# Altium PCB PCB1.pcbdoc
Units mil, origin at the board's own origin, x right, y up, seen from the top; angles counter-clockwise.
Board outline 2165 x 2756 mil, 2 copper layers (Top Layer, Bottom Layer), stack 62.206 mil thick; 92 components, 43 nets, 262 pads, 79 vias.
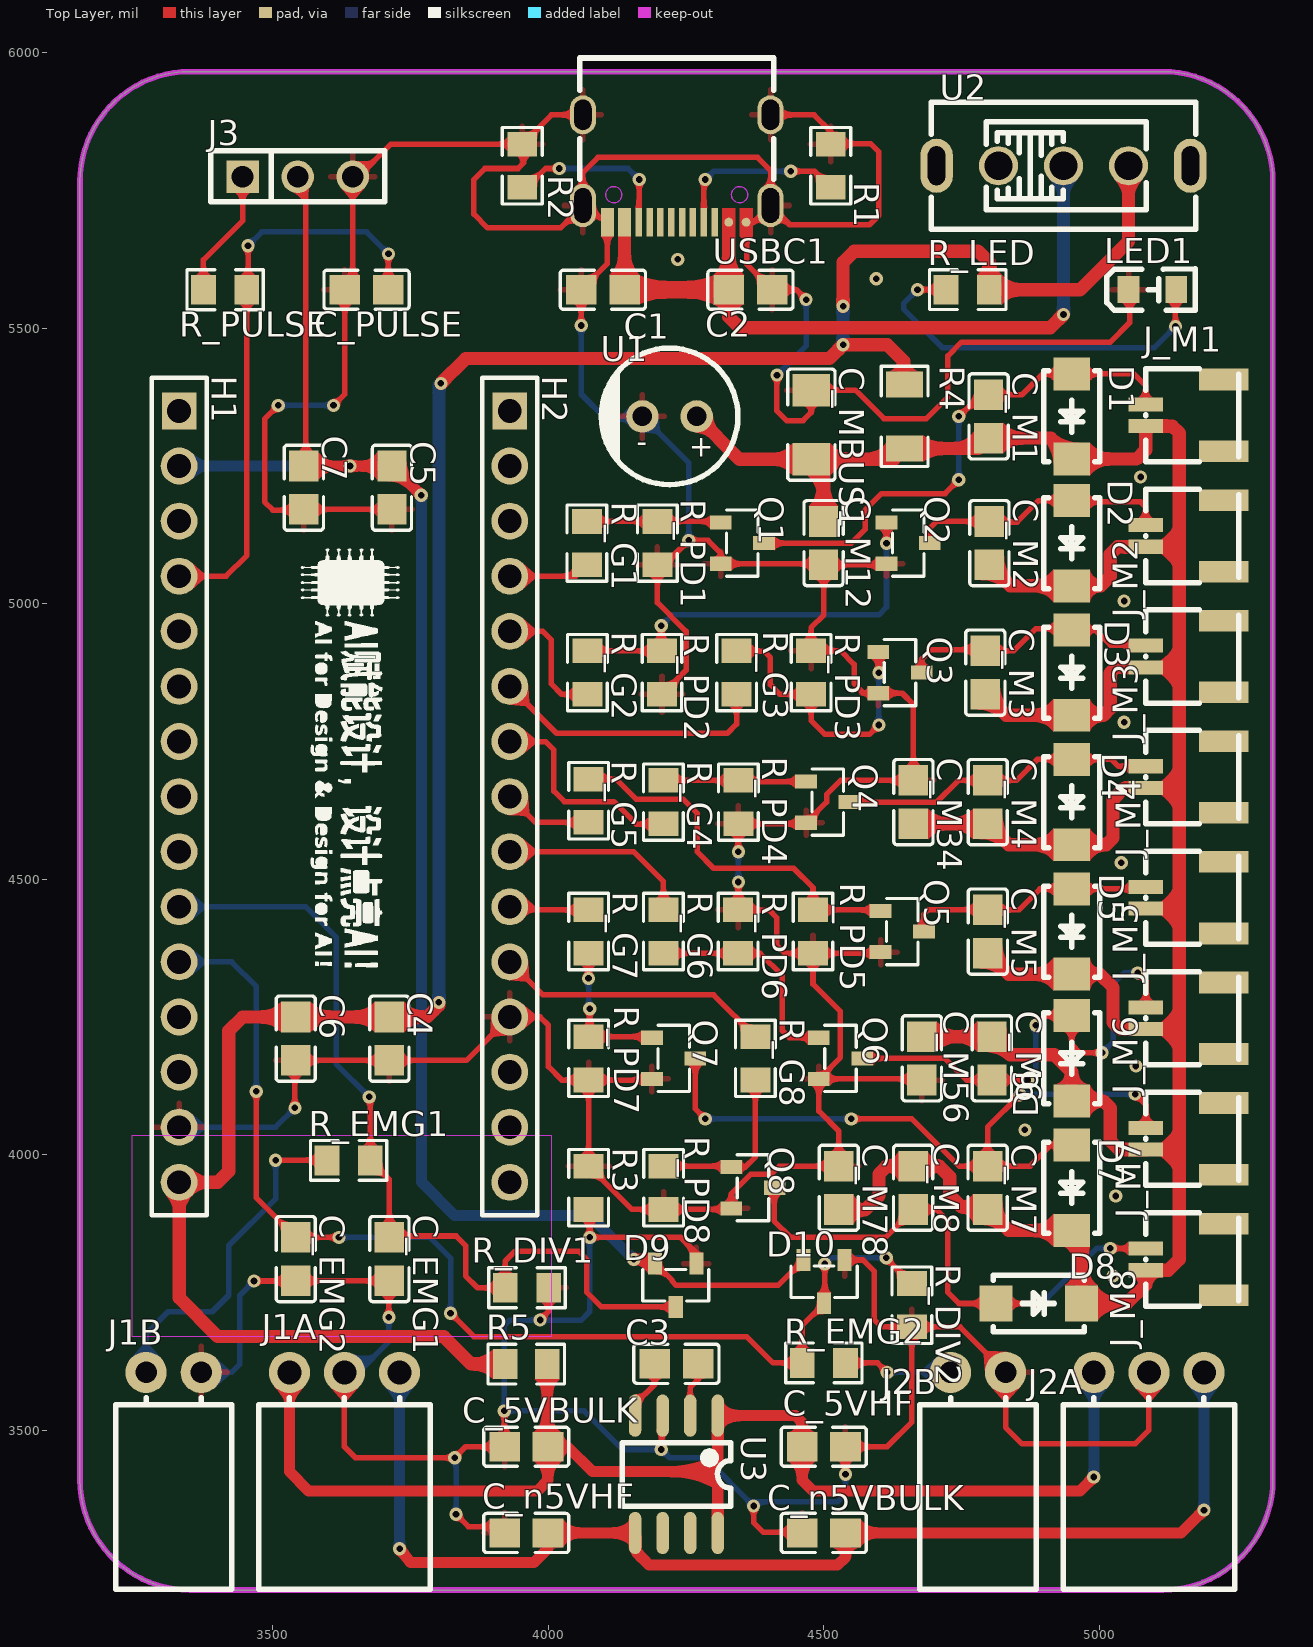
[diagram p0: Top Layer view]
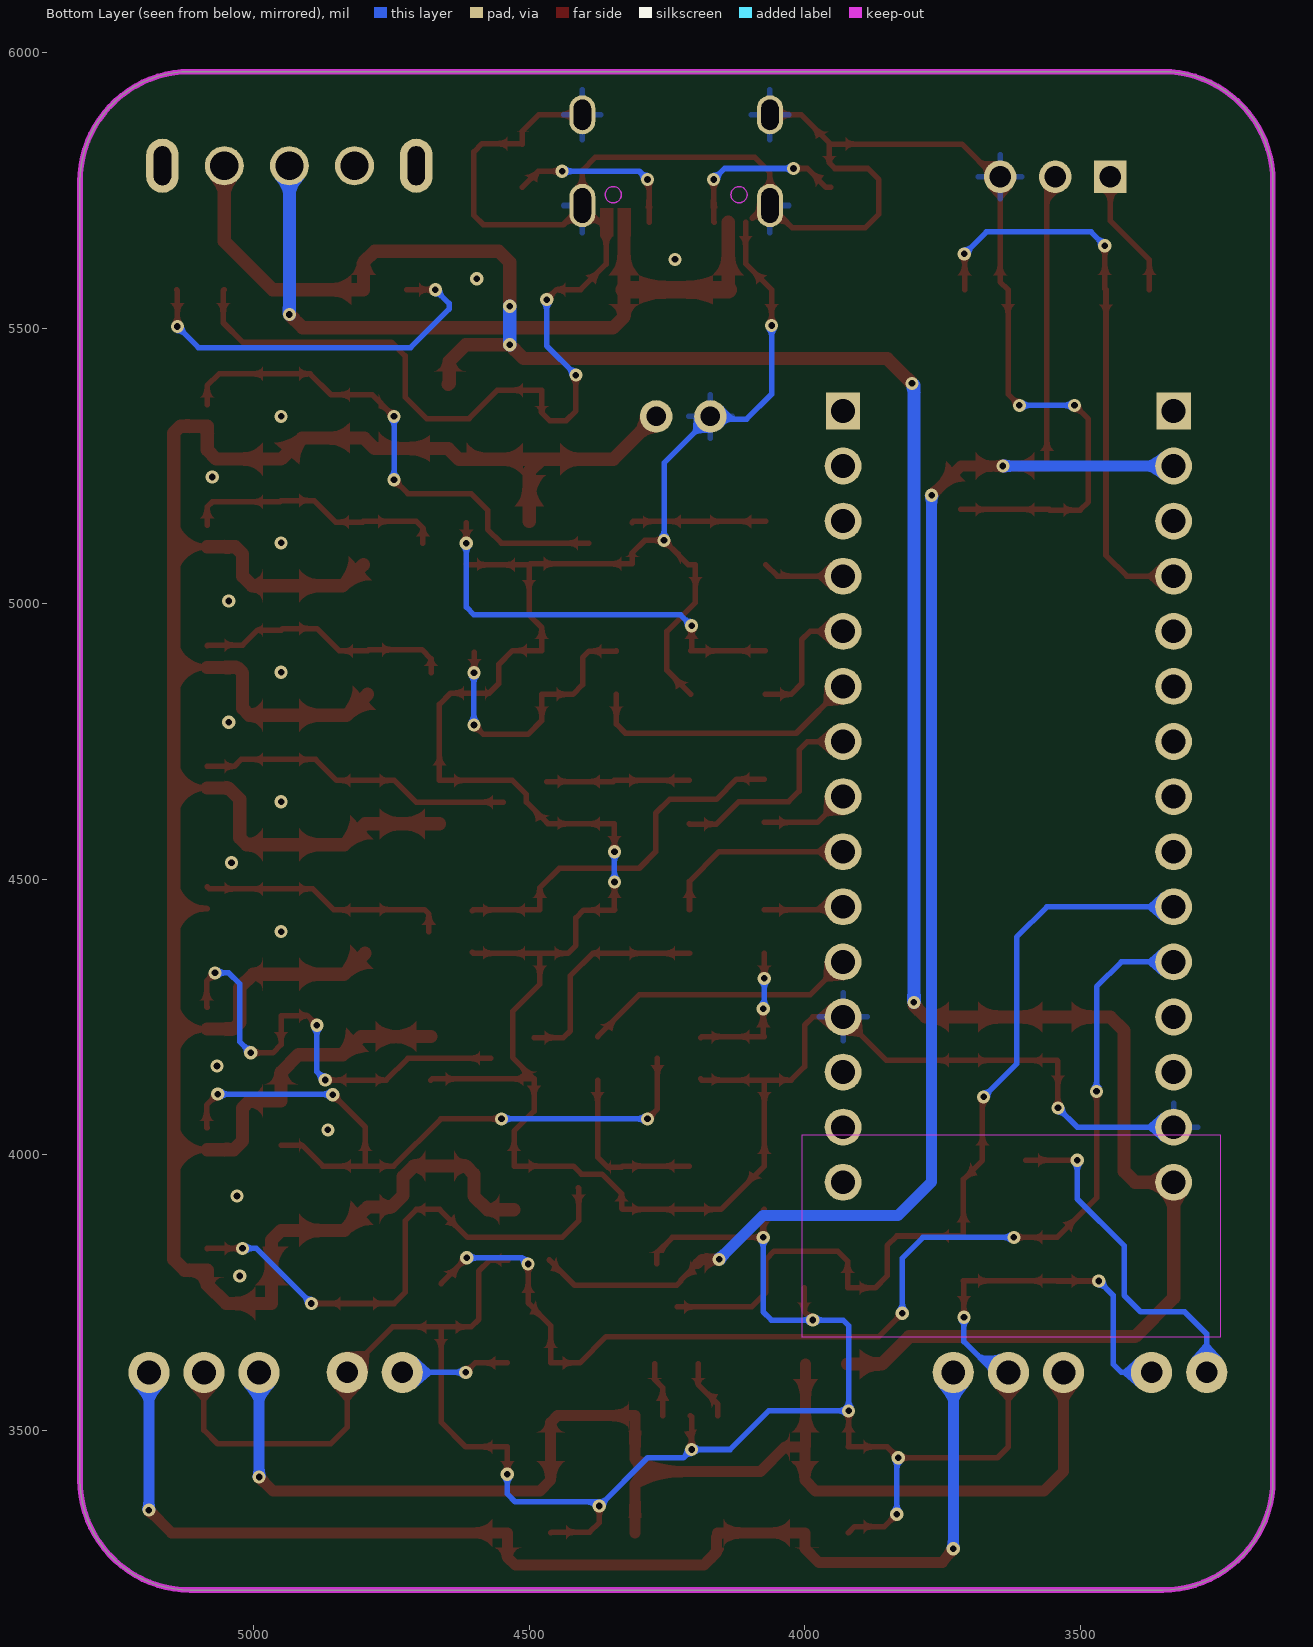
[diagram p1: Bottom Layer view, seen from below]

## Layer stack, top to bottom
Top Solder Mask Layer: solder mask 0.394, Dk 3.3
Top Layer: signal copper 1.379
Dielectric1: surface 59.449, FR4, Dk 4.5
Bottom Layer: signal copper 1.378
Bottom Solder Mask Layer: solder mask 0.394, Dk 3.3

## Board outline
3350.02,5966 5115.02,5966 cw(c5115.02,5766) 5315.02,5766 5315.02,3410 cw(c5115.02,3410) 5115.02,3210 3350.02,3210 cw(c3350.02,3410) 3150.02,3410 3150.02,5766 cw(c3350.02,5766)

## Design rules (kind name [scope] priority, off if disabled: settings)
BoardOutlineClearance copperThickness1oz [All] p0: genericclearance=10 ignorepadtopadclearanceinfootprint=FALSE except(0: Arc-SplitContinuation Track-SplitContinuation SMDPad-SplitContinuation THPad-SplitContinuation Via-SplitContinuation Fill-SplitContinuation Poly-SplitContinuation Region-SplitContinuation Text-SplitContinuation)
BoardOutlineClearance copperThickness2oz [All] p0: genericclearance=10 ignorepadtopadclearanceinfootprint=FALSE except(0: Arc-SplitContinuation Track-SplitContinuation SMDPad-SplitContinuation THPad-SplitContinuation Via-SplitContinuation Fill-SplitContinuation Poly-SplitContinuation Region-SplitContinuation Text-SplitContinuation)
BoardOutlineClearance otherClearance [All] p0: genericclearance=10 ignorepadtopadclearanceinfootprint=FALSE except(0: Arc-SplitContinuation Track-SplitContinuation SMDPad-SplitContinuation THPad-SplitContinuation Via-SplitContinuation Fill-SplitContinuation Poly-SplitContinuation Region-SplitContinuation Text-SplitContinuation)
Clearance copperThickness1oz [All] p1: gap=7 ignorepadtopadclearanceinfootprint=FALSE
Clearance copperThickness2oz [All] p1: gap=7 ignorepadtopadclearanceinfootprint=FALSE
Clearance otherClearance [All] p1: gap=7 ignorepadtopadclearanceinfootprint=FALSE
DiffPairsRouting differentialPair [All] p1: maxuncoupledlength=10 minlimit=6 maxlimit=Infinity mostfreqgap=6 toplayer_minwidth=5 toplayer_prefwidth=10 toplayer_maxwidth=100 bottomlayer_minwidth=5 bottomlayer_prefwidth=10 bottomlayer_maxwidth=100
PasteMaskExpansion pasteMaskExpansion [All] p1: expansion=0
PlaneConnect innerPlane [All] p1: planeconnectstyle=Relief reliefexpansion=20 reliefentries=4 reliefconductorwidth=10 reliefairgap=10
PolygonConnect copperRegion [All] p1: connectstyle=Relief reliefentries=4 reliefconductorwidth=10 polygonreliefangle="90 Angle" airgapwidth=10
RoutingVias viaSize [All] p1: viastyle="Through Hole" holewidth=12.0078 minholewidth=11.811 maxholewidth=248.0314 width=12.0078 minwidth=11.811 maxwidth=248.0314
SolderMaskExpansion solderMaskExpansion [IsVia] p1: useseparateexpansions=TRUE expansion=-1000 expansionbottom=-1000
SolderMaskExpansion solderMaskExpansion [All] p2: useseparateexpansions=TRUE expansion=2 expansionbottom=2
Width copperThickness1oz [All] p1: maxlimit=100 minlimit=5 preferedwidth=10
Width copperThickness2oz [All] p1: maxlimit=100 minlimit=8 preferedwidth=10

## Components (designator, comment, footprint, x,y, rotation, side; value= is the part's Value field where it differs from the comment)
C1 "100nF" C0805 4099.12,5570 r180 top locked
C2 "10uF" C0805 4366.92,5569.99 r0 top locked
C3 "10uF" C0805 4232.52,3620.53 r180 top locked
C4 "10uF" C0805 3711.55,4210.62 r270 top locked
C5 "10uF" C0805 3716.25,5210.65 r270 top locked
C6 "100nF" C0805 3541.55,4210.62 r270 top locked
C7 "100nF" C0805 3556.25,5210.65 r270 top locked
C_5VBULK "10uF" C0805 3960.02,3469.96 r0 top locked
C_5VHF "100nF" C0805 4500,3470 r180 top locked
C_EMG1 "47nF" C0805 3711.55,3810.63 r270 top locked
C_EMG2 "47nF" C0805 3541.55,3810.63 r270 top locked
C_M1 "100nF" C0805 4799.05,5340 r270 top locked
C_M2 "100nF" C0805 4800.53,5110 r270 top locked
C_M3 "100nF" C0805 4793.18,4875 r270 top locked
C_M4 "100nF" C0805 4797.49,4640 r270 top locked
C_M5 "100nF" C0805 4797.67,4405 r270 top locked
C_M6 "100nF" C0805 4805.19,4175 r90 top locked
C_M7 "100nF" C0805 4797.32,3940 r270 top locked
C_M8 "100nF" C0805 4662.22,3940 r90 top locked
C_M12 "10uF" C0805 4499.51,5110 r90 top locked
C_M34 "10uF" C0805 4662.57,4640 r270 top locked
C_M56 "10uF" C0805 4677.97,4175 r90 top locked
C_M78 "10uF" C0805 4527.12,3940 r270 top locked
C_MBUS1 "CC1206X5R10V107MN" C1206 4477.32,5325 r270 top locked
C_n5VBULK "10uF" C0805 4500,3313.49 r0 top locked
C_n5VHF "100nF" C0805 3960.02,3313.5 r0 top locked
C_PULSE "100nF" C0805 3670.02,5570 r0 top locked
D1 "SS14" SMA_L4.2-W2.6-LS5.0-RD_1 4950.02,5340 r90 top locked
D2 "SS14" SMA_L4.2-W2.6-LS5.0-RD_1 4950.02,5110 r90 top locked
D3 "SS14" SMA_L4.2-W2.6-LS5.0-RD_1 4950.02,4875 r90 top locked
D4 "SS14" SMA_L4.2-W2.6-LS5.0-RD_1 4950.02,4640 r90 top locked
D5 "SS14" SMA_L4.2-W2.6-LS5.0-RD_1 4950.02,4405 r90 top locked
D6 "SS14" SMA_L4.2-W2.6-LS5.0-RD_1 4950.02,4175 r90 top locked
D7 "SS14" SMA_L4.2-W2.6-LS5.0-RD_1 4950.02,3940 r90 top locked
D8 "SS14" SMA_L4.2-W2.6-LS5.0-RD_1 4890.02,3730 r180 top locked
D9 "BAT54SLT1" SOT-23-3_L2.9-W1.3-P1.90-LS2.4-BR 4231.25,3763.14 r90 top locked
D10 "BAT54SLT1" SOT-23-3_L2.9-W1.3-P1.90-LS2.4-BR 4500.44,3769.57 r90 top locked
H1 "排母1X15P 2.54mm" HDR-TH_15P-P2.54-V-F 3330.02,4650 r270 top locked
H2 "排母1X15P 2.54mm" HDR-TH_15P-P2.54-V-F 3930.02,4650 r270 top locked
J1A "PM254-1-03-W-8.5" HDR-TH_3P-P2.54-H-F-W10.0-N 3630.02,3605 r0 top locked
J1B "PM254-1-02-W-8.5" HDR-TH_2P-P2.54-H-F-W10.0-N 3320.02,3605 r0 top locked
J2A "PM254-1-03-W-8.5" HDR-TH_3P-P2.54-H-F-W10.0-N 5090.02,3605 r0 top locked
J2B "PM254-1-02-W-8.5" HDR-TH_2P-P2.54-H-F-W10.0-N 4780.02,3605 r0 top locked
J3 "排母2.54mm 1X3pin" HDR-TH_3P-P2.54_CS-1165SDIG 3545.02,5775 r0 top locked
J_M1 "1.0WT-2P" CONN-SMD_2P-P1.00-WT 5155.02,5341.97 r90 top locked
J_M2 "1.0WT-2P" CONN-SMD_2P-P1.00-WT 5155.02,5123.12 r90 top locked
J_M3 "1.0WT-2P" CONN-SMD_2P-P1.00-WT 5155.02,4904.26 r90 top locked
J_M4 "1.0WT-2P" CONN-SMD_2P-P1.00-WT 5155.02,4685.41 r90 top locked
J_M5 "1.0WT-2P" CONN-SMD_2P-P1.00-WT 5155.02,4466.56 r90 top locked
J_M6 "1.0WT-2P" CONN-SMD_2P-P1.00-WT 5155.02,4247.71 r90 top locked
J_M7 "1.0WT-2P" CONN-SMD_2P-P1.00-WT 5155.02,4028.85 r90 top locked
J_M8 "1.0WT-2P" CONN-SMD_2P-P1.00-WT 5155.02,3810 r90 top locked
LED1 "NCD0805R1" LED0805-RD 5096.5,5570.04 r0 top locked
Q1 "AO3400A" SOT-23-3_L2.9-W1.3-P1.90-LS2.4-BR 4352.15,5110 r180 top locked
Q2 "AO3400A" SOT-23-3_L2.9-W1.3-P1.90-LS2.4-BR 4653.17,5110 r180 top locked
Q3 "AO3400A" SOT-23-3_L2.9-W1.3-P1.90-LS2.4-BR 4638.47,4875 r180 top locked
Q4 "AO3400A" SOT-23-3_L2.9-W1.3-P1.90-LS2.4-BR 4507.18,4640 r180 top locked
Q5 "AO3400A" SOT-23-3_L2.9-W1.3-P1.90-LS2.4-BR 4642.45,4405 r180 top locked
Q6 "AO3400A" SOT-23-3_L2.9-W1.3-P1.90-LS2.4-BR 4530.28,4175 r180 top locked
Q7 "AO3400A" SOT-23-3_L2.9-W1.3-P1.90-LS2.4-BR 4227.51,4175 r180 top locked
Q8 "AO3400A" SOT-23-3_L2.9-W1.3-P1.90-LS2.4-BR 4371.55,3940 r180 top locked
R1 "5.1kΩ" R0805 4512.64,5794.98 r90 top locked
R2 "5.1kΩ" R0805 3952.64,5794.98 r270 top locked
R3 "0Ω" R0805 4072.98,3940 r270 top locked
R4 "0Ω" R1206 4646.8,5340 r90 top locked
R5 "10Ω" R0805_NEW 3960.02,3620 r0 top locked
R_DIV1 "10kΩ" R0805 3961.18,3758.55 r180 top locked
R_DIV2 "10kΩ" R0805 4659.78,3726.89 r90 top locked
R_EMG1 "5.6kΩ" R0805 3637.64,3989.76 r0 top locked
R_EMG2 "5.6kΩ" R0805 4500.05,3622.17 r180 top locked
R_G1 "100Ω" R0805 4070.02,5110 r90 top locked
R_G2 "100Ω" R0805 4071.04,4875 r90 top locked
R_G3 "100Ω" R0805 4341.63,4875 r90 top locked
R_G4 "100Ω" R0805 4208.96,4640 r90 top locked
R_G5 "100Ω" R0805 4072.98,4642.52 r90 top locked
R_G6 "100Ω" R0805 4208.79,4405 r270 top locked
R_G7 "100Ω" R0805 4072.98,4405 r270 top locked
R_G8 "100Ω" R0805 4375.74,4175 r270 top locked
R_LED "1kΩ" R0805 4761.2,5570.05 r0 top locked
R_PD1 "10kΩ" R0805 4197.96,5110 r90 top locked
R_PD2 "10kΩ" R0805 4206.34,4875 r90 top locked
R_PD3 "10kΩ" R0805 4476.92,4875 r270 top locked
R_PD4 "10kΩ" R0805 4344.94,4640 r90 top locked
R_PD5 "10kΩ" R0805 4480.39,4405 r90 top locked
R_PD6 "10kΩ" R0805 4344.59,4405 r270 top locked
R_PD7 "10kΩ" R0805 4072.98,4175 r90 top locked
R_PD8 "10kΩ" R0805 4209.14,3940 r90 top locked
R_PULSE "1kΩ" R0805 3413.48,5569.96 r0 top locked
U1 "220uF±20%25V 6.3*11 2.5mm" CAP-TH_BD6.3-P2.50-D0.5-FD 4220.02,5340 r180 top locked
U2 "SS-12F44-G3" SW-TH_SS-12F44-G5_C2998807 4935.02,5795 r0 top locked
U3 "MAX660M/NOPB" SOIC-8_L5.0-W4.0-P1.27-LS6.1-BL 4232.52,3420 r180 top locked
USBC1 "TYPE-C-31-M-12" USB-C_SMD-TYPE-C-31-M-12_1 4233.02,5790 r180 top locked

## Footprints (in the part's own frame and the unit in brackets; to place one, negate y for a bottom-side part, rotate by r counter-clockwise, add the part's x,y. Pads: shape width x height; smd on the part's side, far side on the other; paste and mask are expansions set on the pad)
C0805 [mm]
  rect 1.41x1.35 smd paste-100 mask+0.051: 1(-1,0) 2(1,0)
  silkscreen extent -1.96,-0.9 1.96,0.9
C1206 [mm]
  rect 1.485x1.728 smd paste-100 mask+0.051: 1(-1.593,0) 2(1.593,0)
  silkscreen extent -2.56,-1.09 2.56,1.09
CAP-TH_BD6.3-P2.50-D0.5-FD [mm]
  round 1.5 hole 0.9 paste+0 mask+0.05: 1(-1.25,0) 2(1.25,0)
  silkscreen extent -3.15,-3.15 3.21,3.15
CONN-SMD_2P-P1.00-WT [mm]
  rect 0.65x1.6 smd paste+0 mask+0.05: 1(-0.5,1.8) 2(0.5,1.8)
  rect 1x2.3 smd paste+0 mask+0.05: 5(1.65,-1.8) 6(-1.65,-1.8)
  silkscreen extent -2.15,-2.5 2.15,1.8
HDR-TH_2P-P2.54-H-F-W10.0-N [mm]
  round 1.9 hole 1 paste+0 mask+0.05: 1(-1.27,0) 2(1.27,0)
  silkscreen extent -2.68,-10 2.68,-1.18
HDR-TH_3P-P2.54-H-F-W10.0-N [mm]
  round 1.9 hole 1.1 paste+0 mask+0.05: 1(-2.54,0) 2(0,0) 3(2.54,0)
  silkscreen extent -3.95,-10 3.95,-1.18
HDR-TH_3P-P2.54_CS-1165SDIG [mm]
  rect 1.5x1.5 hole 1: 1(-2.54,0)
  round 1.5 hole 1: 2(0,0) 3(2.54,0)
  silkscreen extent -4.02,-1.15 4.02,1.2
HDR-TH_15P-P2.54-V-F [mm]
  rect 1.7x1.575 hole 1.1: 1(-17.78,0)
  round 1.7 hole 1.1: 2(-15.24,0) 3(-12.7,0) 4(-10.16,0) 5(-7.62,0) 6(-5.08,0) 7(-2.54,0) 8(0,0) 9(2.54,0) 10(5.08,0) 11(7.62,0) 12(10.16,0) 13(12.7,0) 14(15.24,0) 15(17.78,0)
  silkscreen extent -19.3,-1.27 19.3,1.27
LED0805-RD [mm]
  rect 1x1.25 smd: 1(-1.1,0) 2(1.1,0)
  silkscreen extent -2.1,-0.95 1.98,0.96
R0805 [mm]
  rect 1.133x1.377 smd paste-100 mask+0.051: 1(-1,0) 2(1,0)
  silkscreen extent -1.76,-0.92 1.76,0.92
R0805_NEW [mil]
  rect 44.59x54.21 smd paste-3937.01 mask+2: 1(-38.04,0) 2(38.04,0)
  silkscreen extent -69,-36 69,36
R1206 [mil]
  rect 47.54x66.97 smd paste-3937.01 mask+2: 1(-58.22,0) 2(58.22,0)
  silkscreen extent -91,-42 91,42
SMA_L4.2-W2.6-LS5.0-RD_1 [mm]
  rect 1.52x1.68 smd: 1(-1.965,0) 2(1.965,0)
  silkscreen extent -2.1,-1.3 2.1,1.3
SOIC-8_L5.0-W4.0-P1.27-LS6.1-BL [mil]
  oval 22.38x76.78 smd: 1(-75,-106.5) 2(-25,-106.5) 3(25,-106.5) 4(75,-106.5) 5(75,106.5) 6(25,106.5) 7(-25,106.5) 8(-75,106.5)
  silkscreen extent -98,-58 98,58
SOT-23-3_L2.9-W1.3-P1.90-LS2.4-BR [mm]
  rect 1x0.65 smd: 1(1,-0.95) 2(1,0.95) 3(-1,0)
  silkscreen extent -0.73,-1.53 0.73,1.53
SW-TH_SS-12F44-G5_C2998807 [mm]
  round 1.8 hole 1.3: 1(-3,0) 2(0,0) 3(3,0)
  oval 1.5x2.5 hole 0.8 slot 1.8 at 90 deg: 4(5.85,0) 5(-5.85,0)
  silkscreen extent -6.1,-2.92 6.1,2.92
USB-C_SMD-TYPE-C-31-M-12_1 [mm]
  oval 1.2x2 hole 0.8 slot 1.6 at 90 deg: 1(4.325,1.706) 4(-4.325,1.706)
  oval 1.2x1.8 hole 0.8 slot 1.4 at 90 deg copper offset 0,0: 2(4.325,-2.474) 3(-4.325,-2.474)
  round 0.41 smd: A1B12(-3.2,2.474)
  round 0.411 smd: A4B9(-2.4,2.474)
  rect 0.3x1.3 smd paste-100 mask+0.051: A5(-1.25,2.474) A6(-0.25,2.474) A7(0.25,2.474) A8(1.25,2.474) B5(1.75,2.474) B6(0.75,2.474) B7(-0.75,2.474) B8(-1.75,2.474)
  rect 0.6x1.3 smd paste-100 mask+0.051: B1A12(3.2,2.474) B4A9(2.4,2.474)
  Top Layer region: -2.9,1.824 -2.9,3.124 -3.2,3.124 -3.2,3.124 -3.5,3.124 -3.5,1.824 -3.2,1.824 -3.2,1.824
  Top Layer region: -2.1,1.824 -2.1,3.124 -2.4,3.124 -2.4,3.124 -2.7,3.124 -2.7,1.824 -2.4,1.824 -2.4,1.824
  Board Outline Layer circle w0.003: c-2.9,1.206 r0.375
  Board Outline Layer circle w0.003: c2.9,1.206 r0.375
  Board Outline Layer region: -3.275,1.206 -3.238,1.368 -3.134,1.499 -2.983,1.571 -2.816,1.571 -2.666,1.499 -2.562,1.368 -2.525,1.206 -2.525,1.206 -2.562,1.043 -2.666,0.912 -2.816,0.84 -2.983,0.84 -3.134,0.912 -3.238,1.043 -3.275,1.206
  Board Outline Layer region: -3.275,1.206 -3.238,1.368 -3.134,1.499 -2.983,1.571 -2.816,1.571 -2.666,1.499 -2.562,1.368 -2.525,1.206 -2.525,1.206 -2.562,1.043 -2.666,0.912 -2.816,0.84 -2.983,0.84 -3.134,0.912 -3.238,1.043 -3.275,1.206
  Board Outline Layer region: 2.525,1.206 2.562,1.368 2.666,1.499 2.816,1.571 2.983,1.571 3.134,1.499 3.238,1.368 3.275,1.206 3.275,1.206 3.238,1.043 3.134,0.912 2.983,0.84 2.816,0.84 2.666,0.912 2.562,1.043 2.525,1.206
  Board Outline Layer region: 2.525,1.206 2.562,1.368 2.666,1.499 2.816,1.571 2.983,1.571 3.134,1.499 3.238,1.368 3.275,1.206 3.275,1.206 3.238,1.043 3.134,0.912 2.983,0.84 2.816,0.84 2.666,0.912 2.562,1.043 2.525,1.206
  silkscreen extent -4.47,-5.09 4.47,0.49

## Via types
v1: diameter 24.02, hole 12.01, Top Layer to Bottom Layer, 79 vias

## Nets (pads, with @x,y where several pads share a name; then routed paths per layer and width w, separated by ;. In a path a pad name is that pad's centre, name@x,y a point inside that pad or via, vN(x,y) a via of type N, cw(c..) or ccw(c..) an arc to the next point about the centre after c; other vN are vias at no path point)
3V3: C5.1 C7.1 D9.2 D10.2 H1.2 J3.2 | length 3115.4
  Top Layer w10: J3.2 3560.02,5760 3560.02,5253.79 C7.1 ; D9.2 4225.02,3771.35 4225.02,3770 4232.09,3762.93 4417.03,3762.93 D10.2
  Top Layer w20: C7.1 v1(3640.02,5250.02) C5.1 v1(3769.45,5196.82) ; v1(4155.02,3810) 4186.36,3810 D9.2
  Bottom Layer w20: H1.2 v1(3640.02,5250.02) ; v1(3769.45,5196.82) 3769.45,3950.56 3830.02,3890 4075.02,3890 v1(4155.02,3810)
$1N21: Q5.1 R_G5.2 R_PD5.2 | length 693.9
  Top Layer w10: R_G5.2 4123.13,4681.89 4160.02,4645 4245.02,4645 4270.02,4620 4270.02,4550 4300.02,4520 4445.02,4520 4480.39,4484.62 R_PD5.2 4601.11,4444.37 Q5.1
$1N22: Q7.1 R_G7.2 R_PD7.2 | length 268.9
  Top Layer w10: v1(4072.98,4320) R_G7.2 ; v1(4075.02,4265) 4075.02,4216.4 R_PD7.2 4186.17,4214.37 Q7.1
  Bottom Layer w10: v1(4072.98,4320) 4072.98,4267.03 v1(4075.02,4265)
$1N23: Q6.1 R_G6.2 R_PD6.2 | length 404.2
  Top Layer w10: R_G6.2 R_PD6.2 4384.39,4365.63 4425.02,4325 4425.02,4225 4437.52,4212.5 4490.81,4212.5 Q6.1
$1N24: Q2.1 R_G2.2 R_PD2.2 | length 757.9
  Top Layer w10: R_G2.2 R_PD2.2 4205.02,4915.69 v1(4205.02,4960) ; v1(4613.8,5110) Q2.1
  Bottom Layer w10: v1(4205.02,4960) 4225.02,4980 4600.02,4980 4613.8,4993.78 v1(4613.8,5110)
$1N25: Q8.1 R_G8.2 R_PD8.2 | length 314.9
  Top Layer w10: R_PD8.2 4330.21,3979.37 Q8.1 4357.42,3977.4 4375.74,3995.73 R_G8.2
$1N26: Q1.1 R_G1.2 R_PD1.2 | length 243.6
  Top Layer w10: R_G1.2 R_PD1.2 4310.81,5149.37 Q1.1
$1N27: Q4.1 R_G4.2 R_PD4.2 | length 259.7
  Top Layer w10: R_G4.2 R_PD4.2 4346.91,4677.4 Q4.1
$1N28: Q3.1 R_G3.2 R_PD3.2 | length 517.5
  Top Layer w10: R_G3.2 4342.04,4913.96 4391.05,4913.96 4402.95,4902.07 4402.95,4853.05 4420.37,4835.63 R_PD3.2 4476.92,4788.09 4502.09,4762.93 4582.95,4762.93 v1(4600.02,4780) ; Q3.1 4599.1,4875.92 v1(4600.02,4875)
  Bottom Layer w10: v1(4600.02,4780) v1(4600.02,4875)
$1N29: C_M1.1 D1.2 J_M1.2 Q1.3 | length 951.1
  Top Layer w10: Q1.3 4550.02,5110 4575.02,5135 4575.02,5170 4605.02,5200 4720.02,5200 v1(4745.02,5225) ; v1(4745.02,5340) 4784.65,5379.63 4798.79,5379.63 C_M1.1 4859.39,5379.37 4897.38,5417.36 D1.2 5062.66,5417.36 5084.15,5395.86 J_M1.2
  Bottom Layer w10: v1(4745.02,5225) v1(4745.02,5340)
$1N30: C_M6.1 D6.2 J_M6.2 Q6.3 | length 863.8
  Top Layer w10: Q6.3 4720.02,4175 4759.39,4135.63 C_M6.1 v1(4870.02,4135.63) ; v1(4885.02,4235) 4902.38,4252.36 D6.2 4950.02,4200 4965.02,4185 v1(5005.02,4185) ; v1(5070.02,4330) 5085.02,4315 5085.02,4268.25 J_M6.2
  Bottom Layer w10: v1(4870.02,4135.63) 4885.02,4150.63 v1(4885.02,4235) ; v1(5005.02,4185) 5025.02,4205 5025.02,4310 5045.02,4330 v1(5070.02,4330)
$1N31: C_M8.1 D8.2 J_M8.2 Q8.3 | length 956.3
  Top Layer w10: Q8.3 4410.02,3939.1 4410.02,3880 4440.02,3850 4611.59,3850 C_M8.1 4704.39,3900.63 4725.02,3880 4725.02,3750 4745.02,3730 D8.2 v1(4895.02,3730) ; v1(5020.02,3830) 5083.83,3830 J_M8.2
  Bottom Layer w10: v1(4895.02,3730) 4995.02,3830 v1(5020.02,3830)
$1N32: C_M7.1 D7.2 J_M7.2 Q7.3 | length 1267
  Top Layer w10: Q7.3 4266.88,4083.13 v1(4285.02,4065) ; v1(4550.02,4065) 4660.02,4065 4745.65,3979.37 C_M7.1 ; v1(4856.17,4108.85) 4797.32,4050 C_M7.1 ; D7.2 4912.38,4017.36 4874.39,3979.37 C_M7.1 ; v1(5065.02,4110) 5085.02,4090 5085.02,4049.4 J_M7.2
  Bottom Layer w10: v1(4285.02,4065) v1(4550.02,4065) ; v1(4856.17,4108.85) 4857.32,4110 v1(5065.02,4110)
$1N33: C_M4.1 D4.2 J_M4.2 Q4.3 | length 574.8
  Top Layer w10: Q4.3 4705.02,4640 4744.39,4679.37 C_M4.1 4849.39,4679.37 4887.38,4717.36 D4.2 5022.66,4717.36 5035.02,4705 5084.06,4705 J_M4.2
$1N34: C_M3.1 D3.2 J_M3.2 Q3.3 | length 468.9
  Top Layer w10: Q3.3 4677.84,4900 4694.59,4916.75 4790.8,4916.75 C_M3.1 4844.39,4914.37 4885.02,4955 4947.38,4955 D3.2 4992.66,4952.36 5020.02,4925 5083.09,4925 J_M3.2
$1N35: C_M2.1 D2.2 J_M2.2 Q2.3 | length 478.5
  Top Layer w10: Q2.3 4692.54,5137.52 4704.39,5149.37 C_M2.1 4801.62,5148.29 4850.94,5148.29 4890.02,5187.36 D2.2 4952.38,5185 5075.02,5185 5084.15,5175.86 J_M2.2
$1N36: C_M5.1 D5.2 J_M5.2 Q5.3 | length 455.1
  Top Layer w10: Q5.3 4681.82,4436.8 4690.02,4445 4797.04,4445 C_M5.1 4854.39,4444.37 4892.38,4482.36 D5.2 5080.27,4482.36 J_M5.2
$1N114: R1.1 USBC1.A5 | length 324.6
  Top Layer w10: USBC1.A5 4282.23,5767.21 v1(4285.02,5770) ; v1(4440.02,5785) 4483.25,5785 R1.1
  Bottom Layer w10: v1(4285.02,5770) 4300.02,5785 v1(4440.02,5785)
$1N115: R2.2 USBC1.B5 | length 312.7
  Top Layer w10: R2.2 3960.63,5755.61 3995.02,5790 v1(4020.02,5790) ; USBC1.B5 4165.02,5693.49 v1(4165.02,5770)
  Bottom Layer w10: v1(4020.02,5790) 4145.02,5790 v1(4165.02,5770)
$1N120: LED1.2 R_LED.1 | length 702.7
  Top Layer w10: v1(4670.02,5570.05) R_LED.1 ; v1(5138.27,5503.25) 5138.27,5568.51 LED1.2
  Bottom Layer w10: v1(4670.02,5570.05) 4645.02,5545 4645.02,5535 4715.02,5465 5100.02,5465 v1(5138.27,5503.25)
+5V: C4.1 C6.1 H1.15 R4.2 R5.1 R_LED.2 U2.3 | length 4567.3
  Top Layer w24: v1(3801.46,4276.45) 3801.46,4271.45 3780.01,4249.99 C4.1 C6.1 3445.02,4249.99 3420.02,4224.99 3420.02,3970 3400.02,3950 H1.15 3330.02,3740 3400.02,3670 3810.02,3670 3860.02,3620 R5.1 ; v1(3805.02,5400) 3850.02,5445 4510.02,5445 v1(4535.02,5470) 4615.02,5470 4645.02,5440 4645.02,5400 R4.2 ; v1(4535.02,5540) 4535.02,5620 4555.02,5640 4780.02,5640 4800.57,5619.45 R_LED.2 4965.06,5570.05 5053.13,5658.11 U2.3
  Bottom Layer w10: v1@3801.46,5396.45 v1(3805.02,5400)
  Bottom Layer w24: v1(3801.46,4276.45) v1@3801.46,5396.45 ; v1(4535.02,5470) v1(4535.02,5540)
+5V_A: C_5VBULK.2 C_5VHF.2 J1A.1 J2A.1 R5.2 U3.1 U3.8 | length 2419.9
  Top Layer w20: J1A.1 3530.02,3425 3565.02,3390 3980.02,3390 3999.39,3409.37 C_5VBULK.2 ; R5.2 3998.06,3471.29 C_5VBULK.2 ; U3.8 4307.52,3402.5 4285.02,3425 ; v1(4990.02,3415) 4965.02,3390 4480.02,3390 4460.63,3409.38 C_5VHF.2 4460.63,3514.38 4448.51,3526.5 U3.1 4307.52,3447.5 4285.02,3425 ; C_5VBULK.2 4035.06,3469.96 4080.02,3425 4285.02,3425
  Bottom Layer w20: v1(4990.02,3415) J2A.1
+5V_IN: C1.1 C2.1 U2.2 USBC1.A4B9 USBC1.B4A9 | length 1378.9
  Top Layer w24: C1.1 USBC1.B4A9 ; USBC1.A4B9@4327.55,5692.55 C2.1 4327.55,5521 4347.55,5501 4911.02,5501 v1(4935.02,5525)
  Top Layer w32: C1.1 C2.1@4327.54,5570
  Bottom Layer w24: v1(4935.02,5525) U2.2
+5V_MOTOR: C_M1.2 C_M2.2 C_M3.2 C_M4.2 C_M5.2 C_M6.2 C_M7.2 C_M8.2 C_M12.2 C_M34.2 C_M56.2 C_M78.2 C_MBUS1.2 D1.1 D2.1 D3.1 D4.1 D5.1 D6.1 D7.1 D8.1 J_M1.1 J_M2.1 J_M3.1 J_M4.1 J_M5.1 J_M6.1 J_M7.1 J_M8.1 R4.1 U1.1 | length 6084.3
  Top Layer w10: J_M7.1 5142.19,4009.16 5145.02,4006.34 ; J_M6.1 5143.97,4228.02 5145.02,4226.97 ; J_M5.1 5144.41,4446.87 5145.02,4446.26 ; J_M4.1 5144.33,4665.72 5145.02,4666.41 ; J_M3.1 5144.12,4884.57 5145.02,4885.47 ; J_M2.1 5142.36,5103.43 5145.02,5100.77
  Top Layer w24: U1.1 4346.93,5262.3 C_MBUS1.2 ; C_M12.2 4499.51,5240.11 C_MBUS1.2 ; C_M78.2 4527.75,3900 4575.02,3900 4600.02,3925 4600.02,3965 4614.39,3979.37 C_M8.2 4709.4,3979.37 4728.77,3960 4728.77,3926.25 4750.02,3905 C_M7.2@4792.95,3905 ; C_M34.2 C_M4.2 4835.48,4562.64 D4.1 5012.66,4562.64 5025.02,4575 5025.02,4645 5045.74,4665.72 J_M4.1 ; C_M56.2 C_M6.2 4838.19,4181.37 4918.65,4181.37 4950.02,4150 D6.1 5007.38,4097.64 5020.02,4085 5020.02,4025 5035.85,4009.16 J_M7.1 ; C_M3.2 4831.17,4797.64 D3.1 5007.66,4797.64 5020.02,4810 5020.02,4874.57 5030.02,4884.57 J_M3.1 ; C_M7.2 4835.31,3862.64 D7.1 4967.38,3845.28 D8.1 5050.02,3730 5084.15,3764.14 J_M8.1 5125.33,3790.31 5145.02,3810 5145.02,4006.34 5145.02,4226.97 5145.02,4446.26 5145.02,4666.41 5145.02,4885.47 5145.02,5100.77 5145.02,5310 5132.74,5322.28 J_M1.1 5084.15,5279.14 5067.66,5262.64 D1.1 4912.03,5300.63 C_M1.2 4780.2,5281.78 R4.1 4627.32,5262.3 C_MBUS1.2 ; C_M5.2 4835.66,4327.64 D5.1 5001.02,4327.64 5025.02,4303.64 5025.02,4240 5037,4228.02 J_M6.1 ; C_M2.2 4838.52,5032.64 D2.1 5002.66,5032.64 5020.02,5050 5020.02,5090 5033.44,5103.43 J_M2.1
-5V_A: C_n5VBULK.2 C_n5VHF.2 J1A.3 J2A.3 U3.5 | length 2191.7
  Top Layer w20: v1(3730.02,3285) 3750.02,3260 3974.17,3260 3999.39,3285.22 C_n5VHF.2 U3.5 4157.52,3308.5 4160.02,3306.01 4160.02,3277.72 4182.74,3255 4525.02,3255 4539.37,3269.36 C_n5VBULK.2 5148.51,3313.49 v1(5190.02,3355)
  Bottom Layer w20: v1(3730.02,3285) J1A.3 ; v1(5190.02,3355) J2A.3
AGND: C_5VBULK.1 C_5VHF.1 C_EMG1.2 C_EMG2.2 C_n5VBULK.1 C_n5VHF.1 D9.1 D10.1 J1A.2 J1B.2 J2A.2 J2B.2 R3.2 R_DIV1.1 R_DIV2.1 U3.3 | length 4409.1
  Top Layer w10: v1(3465.84,3770.82) 3541.11,3770.82 C_EMG2.2 C_EMG1.2 3710.67,3770.38 v1(3710.67,3705) ; J1A.2 3630.02,3470 3650.02,3450 v1(3830.02,3450) 3849.98,3469.96 C_5VBULK.1 3920.02,3470.59 v1(3920.02,3535) ; v1(3832.52,3347.5) 3855.02,3325 3909.15,3325 C_n5VHF.1 ; v1(3985.02,3700) 4000.55,3715.53 R_DIV1.1 ; R3.2 4075.02,3898.6 v1(4075.02,3850) 4240.02,3850 4268.65,3821.36 D9.1 ; v1(4205.02,3465) 4205.02,3524 U3.3 ; v1(4372.52,3362.5) 4372.52,3332.5 4390.02,3315 4459.12,3315 C_n5VBULK.1 ; D10.1 4571.07,3808.95 4591.28,3788.74 4591.28,3701.26 4605.02,3687.52 R_DIV2.1 ; v1(4539.37,3420) C_5VHF.1 4615.02,3470 4659.78,3514.77 R_DIV2.1 ; J2A.2 5090.02,3500 5065.02,3475 4860.02,3475 4830.02,3505 J2B.2 4747.5,3687.52 R_DIV2.1
  Bottom Layer w10: J1B.2 3425.02,3605 3440.02,3620 3440.02,3745 v1(3465.84,3770.82) ; J1A.2 3655.02,3605 3710.67,3660.65 v1(3710.67,3705) ; v1(3830.02,3450) 3832.52,3447.5 v1(3832.52,3347.5) ; v1(4075.02,3850) 4075.02,3715 4060.02,3700 v1(3985.02,3700) 3930.02,3700 3920.02,3690 v1(3920.02,3535) 4065.02,3535 4135.02,3465 v1(4205.02,3465) 4220.02,3450 4285.02,3450 v1(4372.52,3362.5) 4380.02,3370 4525.02,3370 4539.37,3384.36 v1(4539.37,3420)
CAP_N: C3.2 U3.4 | length 108.8
  Top Layer w10: U3.4 4157.52,3547.5 4193.15,3583.13 C3.2
CAP_P: C3.1 U3.2 | length 100
  Top Layer w10: U3.2 4257.52,3577.5 4271.89,3591.87 C3.1
DGND: C1.2 C2.2 C4.2 C5.2 C6.2 C7.2 C_M12.1 C_M34.1 C_M56.1 C_M78.1 C_MBUS1.1 C_PULSE.1 H1.14 H2.12 J3.3 LED1.1 Q1.2 Q2.2 Q3.2 Q4.2 Q5.2 Q6.2 Q7.2 Q8.2 R1.2 R2.1 R3.1 R_PD1.1 R_PD2.1 R_PD3.1 R_PD4.1 R_PD5.1 R_PD6.1 R_PD7.1 R_PD8.1 U1.2 USBC1.1 USBC1.2 USBC1.3 USBC1.4 USBC1.A1B12 USBC1.B1A12 | length 9575.6
  Top Layer w10: v1(3510.02,5360) 3485.02,5335 3485.02,5185 3500.02,5170 3554.97,5170 C7.2 C5.2 ; v1(3540.02,4085) 3540.02,4169.71 C6.2 C4.2 3851.26,4171.25 H2.12 3985.02,4250 4000.02,4235 4000.02,4160 4024.39,4135.63 R_PD7.1 ; v1(3610.02,5360) 3630.65,5380.63 C_PULSE.1 3645.02,5584.37 J3.3 3655.02,5775 3714.37,5834.35 R2.1 ; v1(4059.75,5505) C1.2 4107.03,5617.28 USBC1.B1A12 ; USBC1.2 4005.69,5887.4 R2.1 ; 4095.02,5700 4072.17,5722.85 USBC1.1 ; Q7.2 4186.17,4135.63 R_PD7.1 ; R_PD2.1 4250.02,4879.31 4250.02,4950 4197.96,5002.06 R_PD1.1 4210.65,5070.63 v1(4255.02,5115) 4290.02,5115 4312.78,5092.24 Q1.2 4497.54,5072.6 C_M12.1 ; v1(4344.94,4495) 4344.94,4444.72 R_PD6.1 4344.95,4444.01 4401,4444.01 4415.02,4430 4415.02,4380 4429.39,4365.63 R_PD5.1 ; v1(4344.94,4550) R_PD4.1 4465.84,4600.63 Q4.2 4505.02,4639.81 4505.02,4653.95 4530.43,4679.37 C_M34.1 4662.57,4817.44 4642.42,4837.6 Q3.2 4572.42,4837.6 4555.02,4855 4555.02,4890 4530.02,4915 4477.55,4915 R_PD3.1 4476.92,4956.91 4500.02,4980 4500.02,5070.12 C_M12.1 ; USBC1.3 4482.61,5887.4 4512.64,5857.38 R1.2 4513.29,5835 4585.02,5835 4600.02,5820 4600.02,5705 4582.92,5687.9 4438.24,5687.9 USBC1.4 ; v1(4415.02,5415) 4415.02,5350 4432.52,5332.5 4462.52,5332.5 4477.09,5347.07 4477.09,5387.47 C_MBUS1.1 4557.32,5387.7 4608.93,5336.09 4686.11,5336.09 4725.02,5375 4725.02,5450 4750.02,5475 5020.02,5475 5055.02,5510 5055.02,5568.22 LED1.1 ; v1(4467.89,5552.13) 4450.03,5569.99 C2.2 4360.02,5616.27 4360.02,5691.57 USBC1.A1B12 4373.05,5692.6 USBC1.4 ; Q5.2 4601.11,4365.63 R_PD5.1 ; Q2.2 4611.83,5070.63 C_M12.1 ; C_M56.1 4676,4137.6 Q6.2 ; R2.1 3955.02,5831.98 3955.02,5800 3945.02,5790 3885.02,5790 3865.02,5770 3865.02,5707.29 3890.02,5682.29 4022.18,5682.29 USBC1.1 ; USBC1.1 4062.74,5782.72 4090.02,5810 4380.02,5810 4403.3,5786.72 USBC1.4 ; R_PD7.1 R3.1 4151.72,3900.63 R_PD8.1 4330.21,3900.63 Q8.2 4332.18,3929.39 4367.79,3965 4405.02,3965 4419.39,3979.37 C_M78.1 4527.12,4042.89 4490.91,4079.11 Q6.2 ; R_PD5.1 4480.39,4309.62 4530.02,4260 4530.02,4176.71 Q6.2
  Bottom Layer w10: H1.14 3505.02,4050 v1(3540.02,4085) ; v1(3510.02,5360) v1(3610.02,5360) ; v1(4059.75,5505) 4059.75,5380.27 4105.02,5335 4165.81,5335 U1.2 4255.02,5255.79 v1(4255.02,5115) ; v1(4344.94,4495) v1(4344.94,4550) ; v1(4415.02,5415) 4467.89,5467.87 v1(4467.89,5552.13)
  other v1: 5025.02,3780 5030.02,3925 4865.02,4045 5066.43,4161.09 4950.02,4405 5040.02,4530 4950.02,4640.51 5045.02,4785 4950.02,4875.51 5045.02,5005 4950.02,5110.51 5075.02,5230 4950.02,5340 4595.02,5590 4235.02,5625
EMG1_ADC: C_EMG1.1 D9.3 H1.10 R_DIV1.2 R_EMG1.2 | length 1617.5
  Top Layer w10: v1(3675.02,4105) 3677.01,4103.01 R_EMG1.2 3711.55,3955.21 C_EMG1.1 3714.05,3852.5 3832.52,3852.5 3850.02,3835 3850.02,3780 3871.47,3758.55 R_DIV1.2 3921.81,3806.79 3940.02,3825 4055.02,3825 4070.02,3810 4070.02,3750 4096.25,3723.77 D9.3
  Bottom Layer w10: H1.10 3560.02,4450 3615.02,4395 3615.02,4165 v1(3675.02,4105)
EMG1_SIG: J1B.1 R_EMG1.1 | length 627.6
  Top Layer w10: v1@3500.02,3990 3598.03,3990 R_EMG1.1
  Bottom Layer w10: J1B.1 3270.02,3675 3310.02,3715 3390.02,3715 3420.02,3745 3420.02,3835 3505.02,3920 v1(3505.02,3990)
EMG2_ADC: C_EMG2.1 D10.3 H1.11 R_DIV2.2 R_EMG2.2 | length 2093.9
  Top Layer w10: v1(3470.02,4115) 3470.02,3921.53 C_EMG2.1 v1(3620.02,3850) ; v1(3822.52,3712.5) 3865.02,3670 4360.02,3670 4407.85,3622.17 R_EMG2.2 4460.68,3690 4500.44,3729.77 D10.3 4501.78,3731.54 v1(4501.78,3801.76) ; v1(4613.15,3812.89) R_DIV2.2
  Bottom Layer w10: H1.11 3425.02,4350 3470.02,4305 v1(3470.02,4115) ; v1(3620.02,3850) 3785.02,3850 3822.52,3812.5 v1(3822.52,3712.5) ; v1(4501.78,3801.76) 4512.91,3812.89 v1(4613.15,3812.89)
EMG2_SIG: J2B.1 R_EMG2.1 | length 197.7
  Top Layer w10: R_EMG2.1 4597.85,3622.17 v1(4615.02,3605)
  Bottom Layer w10: v1(4615.02,3605) J2B.1
M1_PWM: H2.4 R_G1.1 | length 148.5
  Top Layer w10: H2.4 4049.39,5050 R_G1.1
M2_PWM: H2.5 R_G2.1 | length 235.3
  Top Layer w10: H2.5 3990.02,4950 4005.02,4935 4005.02,4855 4024.39,4835.63 R_G2.1
M3_PWM: H2.6 R_G3.1 | length 507.7
  Top Layer w10: H2.6 4015.02,4765 4325.02,4765 4341.63,4781.61 R_G3.1
M4_PWM: H2.7 R_G4.1 | length 385.3
  Top Layer w10: H2.7 3995.02,4750 4010.02,4735 4010.02,4660 4028.99,4641.03 4118.99,4641.03 4160.02,4600 4208.33,4600 R_G4.1
M5_PWM: H2.8 R_G5.1 | length 162.4
  Top Layer w10: H2.8 3976.87,4603.15 R_G5.1
M6_PWM: H2.9 R_G6.1 | length 352.9
  Top Layer w10: H2.9 4155.02,4550 4208.79,4496.23 R_G6.1
M7_PWM: H2.10 R_G7.1 | length 145.3
  Top Layer w10: H2.10 3935.65,4444.37 R_G7.1
M8_PWM: H2.11 R_G8.1 | length 501.9
  Top Layer w10: H2.11 3990.02,4290 4300.11,4290 R_G8.1
PULSE_ADC: C_PULSE.2 H1.4 R_PULSE.2 | length 1048.8
  Top Layer w10: H1.4 3415.02,5050 3452.85,5087.83 R_PULSE.2 3455.02,5572.13 v1(3455.02,5650) ; C_PULSE.2 3709.39,5634.37 v1(3710.02,5635)
  Bottom Layer w10: v1(3455.02,5650) 3480.02,5675 3670.02,5675 v1(3710.02,5635)
PULSE_SIG: J3.1 R_PULSE.1 | length 234.4
  Top Layer w10: R_PULSE.1 3374.11,5624.09 3445.02,5695 J3.1
pads on no net: H1.1 H1.3 H1.5 H1.6 H1.7 H1.8 H1.9 H1.12 H1.13 H2.1 H2.2 H2.3 H2.13 H2.14 H2.15 J_M1.5 J_M1.6 J_M2.5 J_M2.6 J_M3.5 J_M3.6 J_M4.5 J_M4.6 J_M5.5 J_M5.6 J_M6.5 J_M6.6 J_M7.5 J_M7.6 J_M8.5 J_M8.6 U2.1 U2.4 U2.5 U3.6 U3.7 USBC1.A6 USBC1.A7 USBC1.A8 USBC1.B6 USBC1.B7 USBC1.B8

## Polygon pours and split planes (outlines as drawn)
DGND on Bottom Layer (solid, remove dead copper, pour order 4): 4330.02,3870 4163.23,3870 4125.02,3908.22 4125.02,3950 4021.43,3950 4001.43,3930 3785.02,3930 3745.47,3969.55 3750.02,4065 3549.6,4070.31 3338.04,3858.76 3000,3855 3000,6177.39 3012.62,6177.39 3015.02,6175 5470.02,6175 5470.02,3705 5425.02,3660 4805.02,3660 4725.02,3740 4725.02,3858.7 4340.14,3859.88
DGND on Top Layer (solid, remove dead copper, pour order 0): 4330.02,3880 4163.23,3880 4130.06,3913.18 4130.12,3945 4016.43,3945 4001.43,3930 3785.02,3930 3750.02,3965 3750.02,4065 3550.02,4065 3345.02,3860 3005,3860 3005,6182.39 3017.62,6182.39 3020.02,6180 5475.02,6180 5475.02,3710 5428.95,3675 4808.62,3675 4720.02,3746.89 4720.02,3858.76 4350.13,3859.89
AGND on Top Layer (solid, remove dead copper, pour order 2): 3025.02,3835 3346.45,3835 3552.27,4040.82 3733.28,4040.82 3733.28,3953.27 3779.01,3907.55 4082.04,3904.76 4124.19,3850 4313.11,3850 4352.34,3825.39 4686.45,3825.39 4686.45,3743.57 4790.02,3640 5446.15,3640 5446.15,3013.86 5460.02,3000 3070.02,3000 3025.02,3045

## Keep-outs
Board Outline Layer:
  region: 3245.02,4035 4005.02,4035 4005.02,3670 3245.02,3670
  lines w10: 3150.02,3410 ccw(c3350.02,3410) 3350.02,3210 5115.02,3210 ccw(c5115.02,3410) 5315.02,3410 5315.02,5766 ccw(c5115.02,5766) 5115.02,5966 3350.02,5966 ccw(c3350.02,5766) 3150.02,5766 3150.02,3410

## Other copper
Top Layer:
  drawing of 413 lines, arcs and shapes, not listed
Bottom Layer:
  region net +5V_IN: 4923.02,5539.41 4947.02,5539.41 4947.02,5525 4923.01,5525
  region net +5V_IN: 4947.02,5746.76 4923.02,5746.76 4922.69,5748.68 4921.76,5751.22 4920.33,5754.25 4918.46,5757.61 4916.26,5761.18 4913.79,5764.78 4911.16,5768.29 4908.44,5771.56 4961.59,5771.56 4958.87,5768.29 4956.24,5764.78 4953.78,5761.18 4951.57,5757.61 4949.71,5754.25 4948.27,5751.22 4947.34,5748.68
  region net +5V: 3813.46,5385.44 3789.46,5383.15 3789.56,5383.78 3789.83,5384.41 3790.78,5385.66 3792.09,5386.87 3793.55,5388.03 3796.04,5390.06 3796.62,5390.88 3796.66,5391.24 3796.48,5391.55 3815.33,5393.84 3814.64,5392.24 3814.05,5390.05 3813.62,5387.65
  region net +5V: 3789.46,4290.86 3813.46,4290.86 3813.47,4276.45 3789.46,4276.45
  region net +5V: 4547.02,5525.59 4523.02,5525.59 4523.01,5540 4547.02,5540
  region net +5V: 4523.02,5484.41 4547.02,5484.41 4547.02,5470 4523.01,5470
  region net AGND: 3827.52,3363.85 3837.52,3363.85 3837.86,3362.04 3838.77,3359.77 3840.05,3357.44 3841.52,3355.44 3823.51,3355.44 3824.98,3357.44 3826.26,3359.77 3827.17,3362.04
  region net AGND: 3837.52,3435.7 3827.52,3431.95 3827.41,3432.95 3827.12,3434.07 3826.06,3436.43 3824.57,3438.66 3823.73,3439.6 3822.86,3440.36 3840.48,3444.11 3839.39,3441.91 3838.44,3439.51 3837.77,3437.31
  region net -5V_A: 5180.02,3369.41 5200.02,3369.41 5200.1,3367.25 5200.33,3365.14 5201.02,3361.13 5201.71,3357.67 5202.02,3355 5178.01,3355 5178.32,3357.67 5179.01,3361.13 5179.7,3365.14 5179.93,3367.25
  region net -5V_A: 5200.02,3554.08 5180.02,3554.08 5179.61,3555.61 5178.47,3557.94 5176.69,3560.92 5174.38,3564.4 5168.59,3572.25 5165.33,3576.32 5161.97,3580.26 5218.07,3580.26 5214.7,3576.32 5211.44,3572.25 5205.66,3564.4 5203.35,3560.92 5201.57,3557.94 5200.42,3555.61
  region net +5V_A: 4980.02,3429.41 5000.02,3429.41 5000.1,3427.25 5000.33,3425.14 5001.02,3421.13 5001.71,3417.67 5002.02,3415 4978.01,3415 4978.32,3417.67 4979.01,3421.13 4979.7,3425.14 4979.93,3427.25
  region net +5V_A: 5000.02,3554.08 4980.02,3554.08 4979.61,3555.61 4978.47,3557.94 4976.69,3560.92 4974.38,3564.4 4968.59,3572.25 4965.33,3576.32 4961.97,3580.26 5018.07,3580.26 5014.7,3576.32 5011.44,3572.25 5005.66,3564.4 5003.35,3560.92 5001.57,3557.94 5000.42,3555.61
  region net -5V_A: 3720.02,3299.41 3740.02,3299.41 3740.1,3297.25 3740.33,3295.14 3741.02,3291.13 3741.71,3287.67 3742.02,3285 3718.01,3285 3718.32,3287.67 3719.01,3291.13 3719.7,3295.14 3719.93,3297.25
  region net -5V_A: 3740.02,3554.08 3720.02,3554.08 3719.61,3555.61 3718.47,3557.94 3716.69,3560.92 3714.38,3564.4 3708.59,3572.25 3705.33,3576.32 3701.97,3580.26 3758.07,3580.26 3754.7,3576.32 3751.44,3572.25 3745.66,3564.4 3743.35,3560.92 3741.57,3557.94 3740.42,3555.61
  region net AGND: 4220.11,3456.98 4213.04,3449.9 4211.52,3450.94 4209.27,3451.9 4206.72,3452.64 4204.26,3453.02 4217,3465.75 4217.38,3463.3 4218.12,3460.74 4219.08,3458.5
  region net AGND: 4188.67,3460 4188.67,3470 4190.48,3470.34 4192.74,3471.25 4195.07,3472.53 4197.07,3474.01 4197.07,3455.99 4195.07,3457.47 4192.74,3458.75 4190.48,3459.66
  region net AGND: 3420.94,3610 3420.94,3600 3394.76,3576.95 3394.76,3633.05
  region net AGND: 3457.81,3755.73 3450.74,3762.8 3451.78,3764.32 3452.74,3766.56 3453.48,3769.12 3453.85,3771.57 3466.59,3758.84 3464.14,3758.46 3461.58,3757.72 3459.34,3756.76
  region net AGND: 3715.67,3688.65 3705.67,3688.65 3705.32,3690.46 3704.42,3692.73 3703.13,3695.06 3701.66,3697.06 3719.67,3697.06 3718.2,3695.06 3716.92,3692.73 3716.01,3690.46
  region net AGND: 3682.28,3639.34 3670.61,3613.52 3669.32,3612.04 3668.23,3610.39 3667.31,3608.59 3666.54,3606.69 3665.39,3602.66 3664.6,3598.51 3663.45,3590.78 3662.77,3587.64 3662.34,3586.36 3661.81,3585.29 3645.6,3639 3648,3638 3650.51,3637.14 3655.76,3635.82 3661.13,3635.05 3666.41,3634.82 3671.38,3635.14 3673.68,3635.51 3675.82,3636 3677.78,3636.64 3679.53,3637.4 3681.04,3638.3
  region net AGND: 4544.37,3403.65 4534.37,3403.65 4534.03,3405.46 4533.12,3407.73 4531.84,3410.06 4530.37,3412.06 4548.38,3412.06 4546.91,3410.06 4545.63,3407.73 4544.72,3405.46
  region net AGND: 4381.5,3375 4392.83,3365 4391.35,3364.91 4389.89,3364.65 4388.51,3364.25 4387.25,3363.73 4386.16,3363.12 4385.29,3362.43 4384.7,3361.7 4384.42,3360.94 4373.09,3374.49 4376.67,3374.72
  region net AGND: 4357.42,3370.52 4364.49,3377.6 4366.02,3376.56 4368.26,3375.6 4370.81,3374.86 4373.27,3374.48 4360.53,3361.75 4360.16,3364.2 4359.42,3366.76 4358.46,3369
  region net EMG2_SIG: 4679.1,3600 4679.1,3610 4705.28,3633.05 4705.28,3576.95
  region net EMG2_SIG: 4631.36,3610 4631.36,3600 4629.56,3599.66 4627.29,3598.75 4624.96,3597.47 4622.96,3595.99 4622.96,3614.01 4624.96,3612.53 4627.29,3611.25 4629.56,3610.34
  region net EMG2_ADC: 3817.52,3728.85 3827.52,3728.85 3827.86,3727.04 3828.77,3724.77 3830.05,3722.44 3831.52,3720.44 3813.51,3720.44 3814.98,3722.44 3816.26,3724.77 3817.17,3727.04
  region net EMG2_ADC: 3636.36,3855 3636.36,3845 3634.56,3844.66 3632.29,3843.75 3629.96,3842.47 3627.96,3840.99 3627.96,3859.01 3629.96,3857.53 3632.29,3856.25 3634.56,3855.34
  region net AGND: 3915.02,3551.35 3925.02,3551.35 3925.36,3549.54 3926.27,3547.27 3927.55,3544.94 3929.02,3542.94 3911.01,3542.94 3912.48,3544.94 3913.76,3547.27 3914.67,3549.54
  region net AGND: 3968.67,3695 3968.67,3705 3970.48,3705.34 3972.74,3706.25 3975.07,3707.53 3977.07,3709.01 3977.07,3690.99 3975.07,3692.47 3972.74,3693.75 3970.48,3694.66
  region net AGND: 3936.36,3540 3936.36,3530 3934.56,3529.66 3932.29,3528.75 3929.96,3527.47 3927.96,3525.99 3927.96,3544.01 3929.96,3542.53 3932.29,3541.25 3934.56,3540.34
  region net AGND: 4001.36,3705 4001.36,3695 3999.56,3694.66 3997.29,3693.75 3994.96,3692.47 3992.96,3690.99 3992.96,3709.01 3994.96,3707.53 3997.29,3706.25 3999.56,3705.34
  region net AGND: 4080.02,3833.65 4070.02,3833.65 4069.67,3835.46 4068.76,3837.73 4067.48,3840.06 4066.01,3842.06 4084.02,3842.06 4082.55,3840.06 4081.27,3837.73 4080.36,3835.46
  region net EMG2_ADC: 4596.81,3807.89 4596.81,3817.89 4598.61,3818.23 4600.88,3819.14 4603.21,3820.42 4605.21,3821.9 4605.21,3803.88 4603.21,3805.35 4600.88,3806.64 4598.61,3807.55
  region net EMG2_ADC: 4509.37,3816.42 4516.44,3809.35 4515.56,3807.99 4514.74,3805.88 4514.1,3803.43 4513.76,3801.01 4501.03,3813.75 4503.44,3814.08 4505.9,3814.73 4508.01,3815.55
  region net 3V3: 3779.45,5182.41 3759.45,5182.41 3759.37,5184.57 3759.14,5186.69 3758.45,5190.69 3757.76,5194.16 3757.44,5196.82 3781.46,5196.82 3781.15,5194.16 3780.46,5190.69 3779.77,5186.69 3779.54,5184.57
  region net 3V3: 4137.76,3813.12 4151.9,3827.26 4153.48,3825.8 4155.14,3824.46 4158.46,3822.12 4161.4,3820.16 4163.51,3818.49 4146.53,3801.51 4144.86,3803.62 4142.9,3806.56 4140.56,3809.87 4139.22,3811.53
  region net 3V3: 3625.61,5240.02 3625.61,5260.02 3627.76,5260.11 3629.88,5260.34 3633.88,5261.03 3637.35,5261.72 3640.02,5262.03 3640.02,5238.02 3637.35,5238.33 3633.88,5239.02 3629.88,5239.71 3627.76,5239.94
  region net 3V3: 3375.56,5260.02 3375.59,5240.02 3374.03,5239.68 3371.8,5238.73 3369.05,5237.23 3365.9,5235.3 3362.51,5233.02 3358.99,5230.46 3355.5,5227.73 3352.17,5224.92 3352.13,5275.11 3355.47,5272.3 3358.97,5269.57 3362.48,5267.02 3365.88,5264.74 3369.02,5262.81 3371.78,5261.32 3374,5260.36
  region net DGND: 3593.67,5355 3593.67,5365 3595.48,5365.34 3597.74,5366.25 3600.07,5367.53 3602.07,5369.01 3602.07,5350.99 3600.07,5352.47 3597.74,5353.75 3595.48,5354.66
  region net DGND: 3526.36,5365 3526.36,5355 3524.56,5354.66 3522.29,5353.75 3519.96,5352.47 3517.96,5350.99 3517.96,5369.01 3519.96,5367.53 3522.29,5366.25 3524.56,5365.34
  region net DGND: 4064.75,5488.65 4054.75,5488.65 4054.4,5490.46 4053.49,5492.73 4052.21,5495.06 4050.74,5497.06 4068.75,5497.06 4067.28,5495.06 4066,5492.73 4065.09,5490.46
  region net DGND: 4134.64,5330 4127.14,5340 4127.76,5340.11 4128.55,5340.42 4130.53,5341.59 4132.98,5343.42 4135.76,5345.79 4138.75,5348.59 4141.84,5351.72 4144.9,5355.06 4147.81,5358.52 4155.31,5314.87 4153.51,5316.29 4151.4,5318.37 4146.44,5323.44 4143.66,5325.92 4140.74,5328.01 4139.24,5328.83 4137.72,5329.46 4136.19,5329.86
  region net DGND: 4250.02,5131.35 4260.02,5131.35 4260.36,5129.54 4261.27,5127.27 4262.55,5124.94 4264.02,5122.94 4246.01,5122.94 4247.48,5124.94 4248.76,5127.27 4249.67,5129.54
  region net DGND: 4202.77,5315.11 4195.7,5308.04 4193.15,5308.5 4187.02,5309.14 4168.96,5310.53 4200.28,5341.85 4201.66,5323.79 4202.31,5317.65
  region net DGND: 4472.89,5535.78 4462.89,5535.78 4462.55,5537.59 4461.64,5539.85 4460.36,5542.18 4458.89,5544.18 4476.9,5544.18 4475.43,5542.18 4474.14,5539.85 4473.24,5537.59
  region net DGND: 4423.04,5430.1 4430.11,5423.02 4429.08,5421.5 4428.12,5419.26 4427.38,5416.7 4427,5414.25 4414.26,5426.98 4416.72,5427.36 4419.27,5428.1 4421.52,5429.06
  region net $1N120: 4662.03,5554.94 4654.93,5561.98 4655.96,5563.51 4656.92,5565.75 4657.66,5568.31 4658.03,5570.77 4670.8,5558.06 4668.35,5557.68 4665.79,5556.94 4663.55,5555.98
  region net $1N120: 5130.24,5488.16 5123.17,5495.23 5124.21,5496.75 5125.17,5498.99 5125.91,5501.55 5126.28,5504 5139.02,5491.27 5136.57,5490.89 5134.01,5490.15 5131.77,5489.19
  region net $1N115: 4036.36,5795 4036.36,5785 4034.56,5784.66 4032.29,5783.75 4029.96,5782.47 4027.96,5780.99 4027.96,5799.01 4029.96,5797.53 4032.29,5796.25 4034.56,5795.34
  region net $1N115: 4149.92,5778.02 4156.99,5785.1 4158.52,5784.06 4160.76,5783.1 4163.31,5782.36 4165.77,5781.98 4153.03,5769.25 4152.66,5771.7 4151.92,5774.26 4150.96,5776.5
  region net $1N114: 4423.67,5780 4423.67,5790 4425.48,5790.34 4427.74,5791.25 4430.07,5792.53 4432.07,5794.01 4432.07,5775.99 4430.07,5777.47 4427.74,5778.75 4425.48,5779.66
  region net $1N114: 4293.04,5785.1 4300.11,5778.02 4299.08,5776.5 4298.12,5774.26 4297.38,5771.7 4297,5769.25 4284.26,5781.98 4286.72,5782.36 4289.27,5783.1 4291.52,5784.06
  region net PULSE_ADC: 3463.04,5665.1 3470.11,5658.02 3469.08,5656.5 3468.12,5654.26 3467.38,5651.7 3467,5649.25 3454.26,5661.98 3456.72,5662.36 3459.27,5663.1 3461.52,5664.06
  region net PULSE_ADC: 3694.92,5643.02 3701.99,5650.1 3703.51,5649.06 3705.76,5648.1 3708.31,5647.36 3710.77,5646.98 3698.03,5634.25 3697.66,5636.7 3696.92,5639.26 3695.96,5641.5
  region net EMG2_ADC: 3465.02,4131.35 3475.02,4131.35 3475.36,4129.54 3476.27,4127.27 3477.55,4124.94 3479.02,4122.94 3461.01,4122.94 3462.48,4124.94 3463.76,4127.27 3464.67,4129.54
  region net EMG2_ADC: 3375.58,4355 3375.58,4345 3373.38,4343.27 3368.02,4338.72 3352.15,4324.9 3352.15,4375.1 3368.02,4361.28 3373.38,4356.73
  region net EMG1_ADC: 3659.92,4113.02 3666.99,4120.1 3668.51,4119.06 3670.76,4118.1 3673.31,4117.36 3675.77,4116.98 3663.03,4104.25 3662.66,4106.7 3661.92,4109.26 3660.96,4111.5
  region net EMG1_ADC: 3375.58,4455 3375.58,4445 3373.38,4443.27 3368.02,4438.72 3352.15,4424.9 3352.15,4475.1 3368.02,4461.28 3373.38,4456.73
  region net DGND: 3375.58,4055 3375.58,4045 3373.38,4043.27 3368.02,4038.72 3352.15,4024.9 3352.15,4075.1 3368.02,4061.28 3373.38,4056.73
  region net DGND: 3531.99,4069.9 3524.92,4076.98 3525.96,4078.5 3526.92,4080.74 3527.66,4083.3 3528.03,4085.75 3540.77,4073.02 3538.31,4072.64 3535.76,4071.9 3533.51,4070.94
  region net $1N31: 4903.04,3745.1 4910.11,3738.02 4909.08,3736.5 4908.12,3734.26 4907.38,3731.7 4907,3729.25 4894.26,3741.98 4896.72,3742.36 4899.27,3743.1 4901.52,3744.06
  region net $1N31: 5003.67,3825 5003.67,3835 5005.48,3835.34 5007.74,3836.25 5010.07,3837.53 5012.07,3839.01 5012.07,3820.99 5010.07,3822.47 5007.74,3823.75 5005.48,3824.66
  region net $1N32: 4871.62,4115 4873.34,4105 4872.44,4104.9 4871.4,4104.63 4869.09,4103.64 4866.8,4102.24 4864.93,4100.65 4863.21,4118.58 4865.32,4117.26 4867.69,4116.12 4869.92,4115.31
  region net $1N32: 4533.67,4060 4533.67,4070 4535.48,4070.34 4537.74,4071.25 4540.07,4072.53 4542.07,4074.01 4542.07,4055.99 4540.07,4057.47 4537.74,4058.75 4535.48,4059.66
  region net $1N32: 4301.36,4070 4301.36,4060 4299.56,4059.66 4297.29,4058.75 4294.96,4057.47 4292.96,4055.99 4292.96,4074.01 4294.96,4072.53 4297.29,4071.25 4299.56,4070.34
  region net $1N30: 4878.04,4150.73 4885.11,4143.65 4884.08,4142.13 4883.12,4139.89 4882.38,4137.33 4882,4134.88 4869.26,4147.61 4871.72,4147.99 4874.27,4148.73 4876.52,4149.69
  region net $1N30: 4890.02,4218.65 4880.02,4218.65 4879.67,4220.46 4878.76,4222.73 4877.48,4225.06 4876.01,4227.06 4894.02,4227.06 4892.55,4225.06 4891.27,4222.73 4890.36,4220.46
  region net $1N30: 5013.04,4200.1 5020.11,4193.02 5019.08,4191.5 5018.12,4189.26 5017.38,4186.7 5017,4184.25 5004.26,4196.98 5006.72,4197.36 5009.27,4198.1 5011.52,4199.06
  region net $1N30: 5053.67,4325 5053.67,4335 5055.48,4335.34 5057.74,4336.25 5060.07,4337.53 5062.07,4339.01 5062.07,4320.99 5060.07,4322.47 5057.74,4323.75 5055.48,4324.66
  region net DGND: 4349.94,4533.65 4339.94,4533.65 4339.6,4535.46 4338.69,4537.73 4337.41,4540.06 4335.94,4542.06 4353.95,4542.06 4352.48,4540.06 4351.2,4537.73 4350.29,4535.46
  region net DGND: 4339.94,4511.35 4349.94,4511.35 4350.29,4509.54 4351.2,4507.27 4352.48,4504.94 4353.95,4502.94 4335.94,4502.94 4337.41,4504.94 4338.69,4507.27 4339.6,4509.54
  region net $1N22: 4077.98,4303.65 4067.98,4303.65 4067.64,4305.46 4066.73,4307.73 4065.45,4310.06 4063.98,4312.06 4081.99,4312.06 4080.52,4310.06 4079.23,4307.73 4078.33,4305.46
  region net $1N22: 4067.98,4279.71 4077.98,4282.76 4078.09,4281.79 4078.38,4280.71 4079.41,4278.36 4080.87,4276.11 4082.55,4274.35 4064.8,4271.3 4065.97,4273.48 4066.99,4275.87 4067.71,4278.08
  region net $1N28: 4595.02,4796.35 4605.02,4796.35 4605.36,4794.54 4606.27,4792.27 4607.55,4789.94 4609.02,4787.94 4591.01,4787.94 4592.48,4789.94 4593.76,4792.27 4594.67,4794.54
  region net $1N28: 4605.02,4858.65 4595.02,4858.65 4594.67,4860.46 4593.76,4862.73 4592.48,4865.06 4591.01,4867.06 4609.02,4867.06 4607.55,4865.06 4606.27,4862.73 4605.36,4860.46
  region net $1N24: 4618.8,5093.65 4608.8,5093.65 4608.46,5095.46 4607.55,5097.73 4606.27,5100.06 4604.8,5102.06 4622.81,5102.06 4621.34,5100.06 4620.05,5097.73 4619.15,5095.46
  region net $1N24: 4213.04,4975.1 4220.11,4968.02 4219.08,4966.5 4218.12,4964.26 4217.38,4961.7 4217,4959.25 4204.26,4971.98 4206.72,4972.36 4209.27,4973.1 4211.52,4974.06
  region net $1N29: 4740.02,5241.35 4750.02,5241.35 4750.36,5239.54 4751.27,5237.27 4752.55,5234.94 4754.02,5232.94 4736.01,5232.94 4737.48,5234.94 4738.76,5237.27 4739.67,5239.54
  region net $1N29: 4750.02,5323.65 4740.02,5323.65 4739.67,5325.46 4738.76,5327.73 4737.48,5330.06 4736.01,5332.06 4754.02,5332.06 4752.55,5330.06 4751.27,5327.73 4750.36,5325.46
  region net EMG1_SIG: 3265.02,3655.92 3275.02,3655.92 3298.07,3629.74 3241.97,3629.74
  region net EMG1_SIG: 3510.02,3973.65 3500.02,3973.65 3499.67,3975.46 3498.76,3977.73 3497.48,3980.06 3496.01,3982.06 3514.02,3982.06 3512.55,3980.06 3511.27,3977.73 3510.36,3975.46
  region net $1N32: 5048.67,4105 5048.67,4115 5050.48,4115.34 5052.74,4116.25 5055.07,4117.53 5057.07,4119.01 5057.07,4100.99 5055.07,4102.47 5052.74,4103.75 5050.48,4104.66

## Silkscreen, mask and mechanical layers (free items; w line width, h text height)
Top Silkscreen Layer:
  drawing of 71 lines, arcs and shapes, not listed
